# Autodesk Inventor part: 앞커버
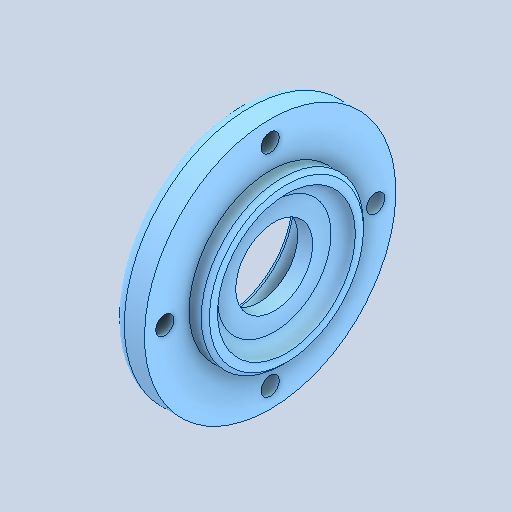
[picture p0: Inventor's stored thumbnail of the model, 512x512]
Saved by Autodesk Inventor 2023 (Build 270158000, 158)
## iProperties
Created: 2024-09
Part Number: 앞커버
Material: 알루미늄 6061
Document SubType Name: Modeling
Designer: home
Density: 2.7 g/cm^3
Appearance: 기본값
Author: jhkim
Sending System: Autodesk Inventor 2025
Preprocessor: ST-DEVELOPER v20
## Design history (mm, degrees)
node "앞커버1"
node "솔리드2"
node "솔리드1"
